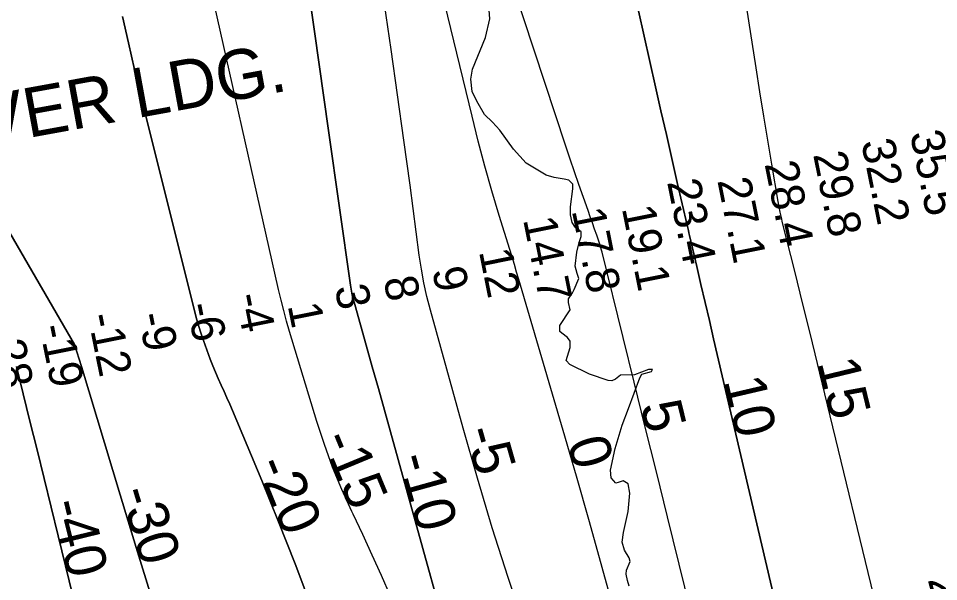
# Model space of a CAD drawing. Extents: x 3161665 to 3199565, y 885729 to 911164.
# Drawn here: x 3177817 to 3179674, y 892537 to 893674 of the extents above; entities that cross this region are included whole.
import ezdxf

# ---------------------------------------------------------------- set-up
doc = ezdxf.new("R2010")
doc.units = 0
for name, color, linetype in [('V-RIVR-EDGE', 7, 'Continuous'), ('V-RIVR-RANG', 7, 'Continuous'), ('V-TOPO-DPTH', 7, 'Continuous'), ('V-TOPO-GNAM-IDEN', 7, 'Continuous'), ('V-TOPO-MAJR-IDEN', 7, 'Continuous'), ('V-TOPO-MINR', 7, 'Continuous'), ('V-TOPO-MINR-IDEN', 7, 'Continuous'), ('V-TOPO-WATR', 7, 'Continuous')]:
    doc.layers.add(name, color=color, linetype=linetype)

msp = doc.modelspace()

# ---------------------------------------------------------------- linework, layer by layer
at = {"layer": 'V-RIVR-EDGE'}
for points in [[(3178730.6, 893551.3), (3178733.7, 893571.7), (3178759.9, 893635.1), (3178768.7, 893672.9), (3178767, 893690.3)], [(3179049.7, 892527.7), (3179046.7, 892539.5), (3179044.1, 892552.1), (3179044.6, 892559.9), (3179052, 892577.7), (3179049.8, 892585.1), (3179040.3, 892600.8), (3179036, 892616.9), (3179038.7, 892636), (3179047.9, 892678.6), (3179051.5, 892715.5), (3179048, 892734.2), (3179037.6, 892740.3), (3179027.6, 892737.3), (3179022.8, 892735.6), (3179013.7, 892746.5), (3179012.5, 892762.1), (3179021.7, 892806), (3179035.7, 892852.5), (3179048.8, 892886.3), (3179071.2, 892948.5), (3179075.5, 892955.8), (3179095.1, 892961), (3179097.3, 892965.3), (3179089, 892965.4), (3179060.7, 892954.1), (3179032.5, 892953.8), (3179022.5, 892946), (3179015.1, 892942.5), (3179007.7, 892943), (3178969.9, 892955.7), (3178930, 892975.3), (3178923, 892983.6), (3178930.9, 893009.7), (3178930.9, 893022.7), (3178925.3, 893030.1), (3178914, 893038.4), (3178910.1, 893041.9), (3178910.2, 893054), (3178930.7, 893085.7), (3178927.7, 893100.1), (3178927.7, 893107.5), (3178935.5, 893120.1), (3178938.6, 893126.6), (3178948.2, 893149.1), (3178945.2, 893159.1), (3178940.9, 893173.9), (3178944, 893202.2), (3178949.3, 893221.3), (3178952.8, 893233.9), (3178952.8, 893243), (3178941.1, 893252.6), (3178935, 893261.8), (3178931.6, 893277.4), (3178931.6, 893293.5), (3178936.1, 893329.6), (3178936.1, 893339.6), (3178928.3, 893347.4), (3178918.7, 893349.2), (3178898.7, 893352.7), (3178882.7, 893357.5), (3178842.3, 893382), (3178816.3, 893409.8), (3178788.6, 893448.6), (3178774.2, 893464.3), (3178757.8, 893480), (3178742.6, 893507), (3178733.1, 893526.5), (3178730.6, 893551.3)]]:
    msp.add_lwpolyline(points, dxfattribs=at)
at = {"layer": 'V-TOPO-DPTH'}
for points in [[(3179011.6, 893945.4), (3179103.2, 893536), (3179114.1, 893487.6), (3179125, 893439.3), (3179136, 893391), (3179147.1, 893342.6), (3179167, 893256.3), (3179168.2, 893251.2), (3179169.4, 893246), (3179170.5, 893240.9), (3179171.7, 893235.8), (3179186.3, 893173.1), (3179194.8, 893136.7), (3179203.3, 893100.3), (3179211.8, 893063.8), (3179220.3, 893027.4), (3179362.5, 892417.9)], [(3179021.1, 892473.3), (3178995.6, 892565.7), (3178969.8, 892658), (3178943.4, 892750.1), (3178916.7, 892842.1), (3178827.3, 893146.7), (3178822.8, 893161.9), (3178818.3, 893177.2), (3178813.6, 893192.4), (3178809, 893207.6), (3178787.8, 893276.3), (3178772.9, 893326), (3178758.7, 893375.9), (3178745.4, 893426), (3178732.7, 893476.3), (3178640.6, 893855.9)], [(3179021.1, 892473.3), (3178995.6, 892565.7), (3178969.8, 892658), (3178943.4, 892750.1), (3178916.7, 892842.1), (3178827.3, 893146.7), (3178822.8, 893161.9), (3178818.3, 893177.2), (3178813.6, 893192.4), (3178809, 893207.6), (3178787.8, 893276.3), (3178772.9, 893326), (3178758.7, 893375.9), (3178745.4, 893426), (3178732.7, 893476.3), (3178640.6, 893855.9)], [(3178732.9, 892244.5), (3178567.9, 892839.2), (3178555.8, 892882.9), (3178543.6, 892926.6), (3178531.4, 892970.3), (3178519.2, 893014), (3178496.2, 893096.3), (3178495.5, 893098.8), (3178494.8, 893101.4), (3178494.1, 893103.9), (3178493.4, 893106.5), (3178492.3, 893110.5), (3178492, 893111.6), (3178491.8, 893112.1), (3178491.7, 893112.7), (3178490.3, 893119.5), (3178489.5, 893123.5), (3178488.7, 893127.5), (3178488.1, 893131.5), (3178487.5, 893135.5), (3178443, 893447.6), (3178433.5, 893514.2), (3178424, 893580.9), (3178414.6, 893647.5), (3178405.1, 893714.1)], [(3178405.1, 893714.1), (3178414.6, 893647.5), (3178424, 893580.9), (3178433.5, 893514.2), (3178443, 893447.6), (3178487.5, 893135.5), (3178488.1, 893131.5), (3178488.7, 893127.5), (3178489.5, 893123.5), (3178490.3, 893119.5), (3178491.7, 893112.7), (3178491.8, 893112.1), (3178492, 893111.6), (3178492.3, 893110.5), (3178493.4, 893106.5), (3178494.1, 893103.9), (3178494.8, 893101.4), (3178495.5, 893098.8), (3178496.2, 893096.3), (3178519.2, 893014), (3178531.4, 892970.3), (3178543.6, 892926.6), (3178555.8, 892882.9), (3178567.9, 892839.2), (3178732.9, 892244.5)], [(3178087.7, 892498.9), (3178054.9, 892605.6), (3178022.4, 892712.4), (3177944.2, 892971.2), (3177939.6, 892986.1), (3177934.9, 893001), (3177930.1, 893015.8), (3177552.7, 893666.6)], [(3177552.7, 893666.6), (3177930.1, 893015.8), (3177934.9, 893001), (3177939.6, 892986.1), (3177944.2, 892971.2), (3178022.4, 892712.4), (3178054.9, 892605.6), (3178087.7, 892498.9)], [(3178027.1, 893678), (3178039.2, 893624.3), (3178051.7, 893570.7), (3178064.5, 893517.2), (3178077.7, 893463.8), (3178176.8, 893067.4), (3178179.1, 893058.7), (3178181.6, 893050), (3178184.4, 893041.5), (3178187.3, 893032.9), (3178204.4, 892986), (3178209.5, 892972.8), (3178214.7, 892959.7), (3178220.4, 892946.7), (3178226.2, 892933.9), (3178232.2, 892921), (3178238, 892908.2), (3178243.7, 892895.2), (3178249.3, 892882.2), (3178308.2, 892741.2), (3178342.4, 892657.4), (3178375.6, 892573.2), (3178407.5, 892488.5)], [(3178027.1, 893678), (3178039.2, 893624.3), (3178051.7, 893570.7), (3178064.5, 893517.2), (3178077.7, 893463.8), (3178176.8, 893067.4), (3178179.1, 893058.7), (3178181.6, 893050), (3178184.4, 893041.5), (3178187.3, 893032.9), (3178204.4, 892986), (3178209.5, 892972.8), (3178214.7, 892959.7), (3178220.4, 892946.7), (3178226.2, 892933.9), (3178232.2, 892921), (3178238, 892908.2), (3178243.7, 892895.2), (3178249.3, 892882.2), (3178308.2, 892741.2), (3178342.4, 892657.4), (3178375.6, 892573.2), (3178407.5, 892488.5)], [(3178605.4, 891160.3), (3178390.2, 891160.9), (3178089.4, 891920.8), (3178084.7, 891929.9), (3178080.5, 891939.1), (3178076.5, 891948.5), (3178051.4, 892011.3), (3178048.2, 892019.8), (3178045.3, 892028.4), (3178042.7, 892037.1), (3178040.3, 892045.9), (3177897.3, 892629.6), (3177883.1, 892687.4), (3177868.9, 892745.3), (3177854.7, 892803.1), (3177840.4, 892860.9), (3177813.2, 892971.3)], [(3177813.2, 892971.3), (3177840.4, 892860.9), (3177854.7, 892803.1), (3177868.9, 892745.3), (3177883.1, 892687.4), (3177897.3, 892629.6), (3178040.3, 892045.9), (3178042.7, 892037.1), (3178045.3, 892028.4), (3178048.2, 892019.8), (3178051.4, 892011.3), (3178076.5, 891948.5), (3178080.5, 891939.1), (3178084.7, 891929.9), (3178089.4, 891920.8), (3178390.2, 891160.9)]]:
    msp.add_lwpolyline(points, dxfattribs=at)
at = {"layer": 'V-TOPO-MINR'}
for points in [[(3179362.5, 892417.9), (3179220.3, 893027.4), (3179211.8, 893063.8), (3179203.3, 893100.3), (3179194.8, 893136.7), (3179186.3, 893173.1), (3179171.7, 893235.8), (3179170.5, 893240.9), (3179169.4, 893246), (3179168.2, 893251.2), (3179167, 893256.3), (3179147.1, 893342.6), (3179136, 893391), (3179125, 893439.3), (3179114.1, 893487.6), (3179103.2, 893536), (3179011.6, 893945.4)], [(3179683.2, 891865.5), (3179656.1, 891988), (3179629.8, 892110.6), (3179577, 892363.4), (3179571.6, 892388.6), (3179566, 892413.8), (3179560.2, 892439), (3179554.3, 892464.2), (3179444.9, 892916.3), (3179430, 892977.5), (3179415.1, 893038.6), (3179400, 893099.6), (3179384.8, 893160.7), (3179359.7, 893261.5), (3179357.2, 893272.2), (3179354.8, 893282.8), (3179352.7, 893293.5), (3179350.7, 893304.3), (3179337.9, 893379.8), (3179329.8, 893428.3), (3179321.8, 893476.8), (3179313.9, 893525.4), (3179306.3, 893574), (3179246.9, 893954.3)], [(3178568.1, 892507.7), (3178549.7, 892549.2), (3178531.1, 892590.6), (3178512, 892631.8), (3178492.6, 892672.9), (3178489.8, 892678.8), (3178469.9, 892723.1), (3178451.3, 892768), (3178434.8, 892813.7), (3178419.6, 892859.9), (3178364.6, 893041.7), (3178358.5, 893062.8), (3178352.6, 893084), (3178347.3, 893105.3), (3178342.2, 893126.7), (3178188.2, 893812.4)], [(3179209, 892337.4), (3179127.3, 892667.7), (3179104.9, 892758.3), (3179082.5, 892848.8), (3179060.1, 892939.3), (3179037.7, 893029.9), (3178995.2, 893201.7), (3178994, 893206.3), (3178992.7, 893210.9), (3178991.3, 893215.5), (3178989.8, 893220.1), (3178984.4, 893236.1), (3178980.1, 893248.6), (3178975.8, 893261.1), (3178971.4, 893273.6), (3178967, 893286.1), (3178957.5, 893312.6), (3178948.4, 893338.3), (3178939.5, 893364.1), (3178930.7, 893390), (3178922.1, 893415.9), (3178816, 893738.9)], [(3178732.9, 892244.5), (3178567.9, 892839.2), (3178555.8, 892882.9), (3178543.6, 892926.6), (3178531.4, 892970.3), (3178519.2, 893014), (3178496.2, 893096.3), (3178495.5, 893098.8), (3178494.8, 893101.4), (3178494.1, 893103.9), (3178493.4, 893106.5), (3178492.3, 893110.5), (3178492, 893111.6), (3178491.8, 893112.1), (3178491.7, 893112.7), (3178490.3, 893119.5), (3178489.5, 893123.5), (3178488.7, 893127.5), (3178488.1, 893131.5), (3178487.5, 893135.5), (3178443, 893447.6), (3178433.5, 893514.2), (3178424, 893580.9), (3178414.6, 893647.5), (3178405.1, 893714.1)], [(3178838.7, 892446.1), (3178805.6, 892545.6), (3178773.7, 892645.6), (3178743.6, 892746.1), (3178714.7, 892847), (3178648.8, 893085), (3178641.8, 893112.5), (3178635.6, 893140.1), (3178630.5, 893167.9), (3178626.2, 893195.9), (3178607.6, 893337), (3178595.3, 893428.4), (3178582.6, 893519.8), (3178569.4, 893611.2), (3178555.8, 893702.4)], [(3177552.7, 893666.6), (3177930.1, 893015.8), (3177934.9, 893001), (3177939.6, 892986.1), (3177944.2, 892971.2), (3178022.4, 892712.4), (3178054.9, 892605.6), (3178087.7, 892498.9)], [(3178407.5, 892488.5), (3178375.6, 892573.2), (3178342.4, 892657.4), (3178308.2, 892741.2), (3178249.3, 892882.2), (3178243.7, 892895.2), (3178238, 892908.2), (3178232.2, 892921), (3178226.2, 892933.9), (3178220.4, 892946.7), (3178214.7, 892959.7), (3178209.5, 892972.8), (3178204.4, 892986), (3178187.3, 893032.9), (3178184.4, 893041.5), (3178181.6, 893050), (3178179.1, 893058.7), (3178176.8, 893067.4), (3178077.7, 893463.8), (3178064.5, 893517.2), (3178051.7, 893570.7), (3178039.2, 893624.3), (3178027.1, 893678)], [(3177813.2, 892971.3), (3177840.4, 892860.9), (3177854.7, 892803.1), (3177868.9, 892745.3), (3177883.1, 892687.4), (3177897.3, 892629.6), (3178040.3, 892045.9), (3178042.7, 892037.1), (3178045.3, 892028.4), (3178048.2, 892019.8), (3178051.4, 892011.3), (3178076.5, 891948.5), (3178080.5, 891939.1), (3178084.7, 891929.9), (3178089.4, 891920.8), (3178390.2, 891160.9)]]:
    msp.add_lwpolyline(points, dxfattribs=at)
at = {"layer": 'V-TOPO-WATR'}
msp.add_lwpolyline([(3179021.1, 892473.3), (3178995.6, 892565.7), (3178969.8, 892658), (3178943.4, 892750.1), (3178916.7, 892842.1), (3178827.3, 893146.7), (3178822.8, 893161.9), (3178818.3, 893177.2), (3178813.6, 893192.4), (3178809, 893207.6), (3178787.8, 893276.3), (3178772.9, 893326), (3178758.7, 893375.9), (3178745.4, 893426), (3178732.7, 893476.3), (3178640.6, 893855.9)], dxfattribs=at)

# ---------------------------------------------------------------- texts
at = {"layer": 'V-RIVR-RANG'}
for s, rotation, p in [('35.5', 281.3703, (3179616.5, 893442)), ('32.2', 281.3703, (3179518, 893424.6)), ('29.8', 281.3703, (3179421.1, 893399.4)), ('28.4', 281.3703, (3179323, 893380.2)), ('27.1', 281.3703, (3179227.7, 893346.8)), ('23.4', 281.3703, (3179126.3, 893343.9)), ('17.8', 281.3703, (3178933.9, 893286.1)), ('19.1', 281.3703, (3179034.9, 893290.8)), ('14.7', 281.3703, (3178835.5, 893268.1)), ('12', 281.3703, (3178746.4, 893203.7)), ('9', 281.3703, (3178651.9, 893166.4)), ('8', 281.3703, (3178553.7, 893147.7)), ('3', 281.3703, (3178455.1, 893130.8)), ('-4', 281.3703, (3178254.4, 893114.4)), ('-6', 281.3703, (3178156.3, 893095.2)), ('1', 281.3703, (3178360.4, 893094.5)), ('-12', 281.3703, (3177956.5, 893073.8)), ('-9', 281.3703, (3178058.2, 893075.4)), ('-19', 281.3703, (3177859, 893051.5)), ('-28', 281.3703, (3177757.5, 893049.4)), ('29.5', 284.3656, (3179652.3, 892541.5))]:
    msp.add_text(s, height=67, rotation=rotation, dxfattribs=at).set_placement(p)
at = {"layer": 'V-TOPO-GNAM-IDEN'}
msp.add_text('RED RIVER LDG.', height=100, rotation=10.3384, dxfattribs=at).set_placement((3177303.2, 893335))
at = {"layer": 'V-TOPO-MAJR-IDEN'}
msp.add_text('0', height=83, rotation=286.1904, dxfattribs=at).set_placement((3178923.8, 892817.6))
at = {"layer": 'V-TOPO-MINR-IDEN'}
for s, rotation, p in [('15', 283.6629, (3179429.5, 892979.4)), ('10', 283.1416, (3179240, 892942.8)), ('5', 283.8903, (3179071.6, 892892.5)), ('-15', 292.4976, (3178427.7, 892825)), ('-5', 285.9887, (3178716.4, 892841)), ('-20', 292.1975, (3178295, 892773.5)), ('-10', 285.507, (3178582.4, 892787.1)), ('-30', 286.9366, (3178020.6, 892718.3)), ('-40', 283.7677, (3177881.1, 892695.7))]:
    msp.add_text(s, height=83, rotation=rotation, dxfattribs=at).set_placement(p)

doc.saveas('drawing.dxf')
